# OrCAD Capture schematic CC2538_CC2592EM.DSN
size A3; title: CC2538-CC2592EM; rev: 2.0.1
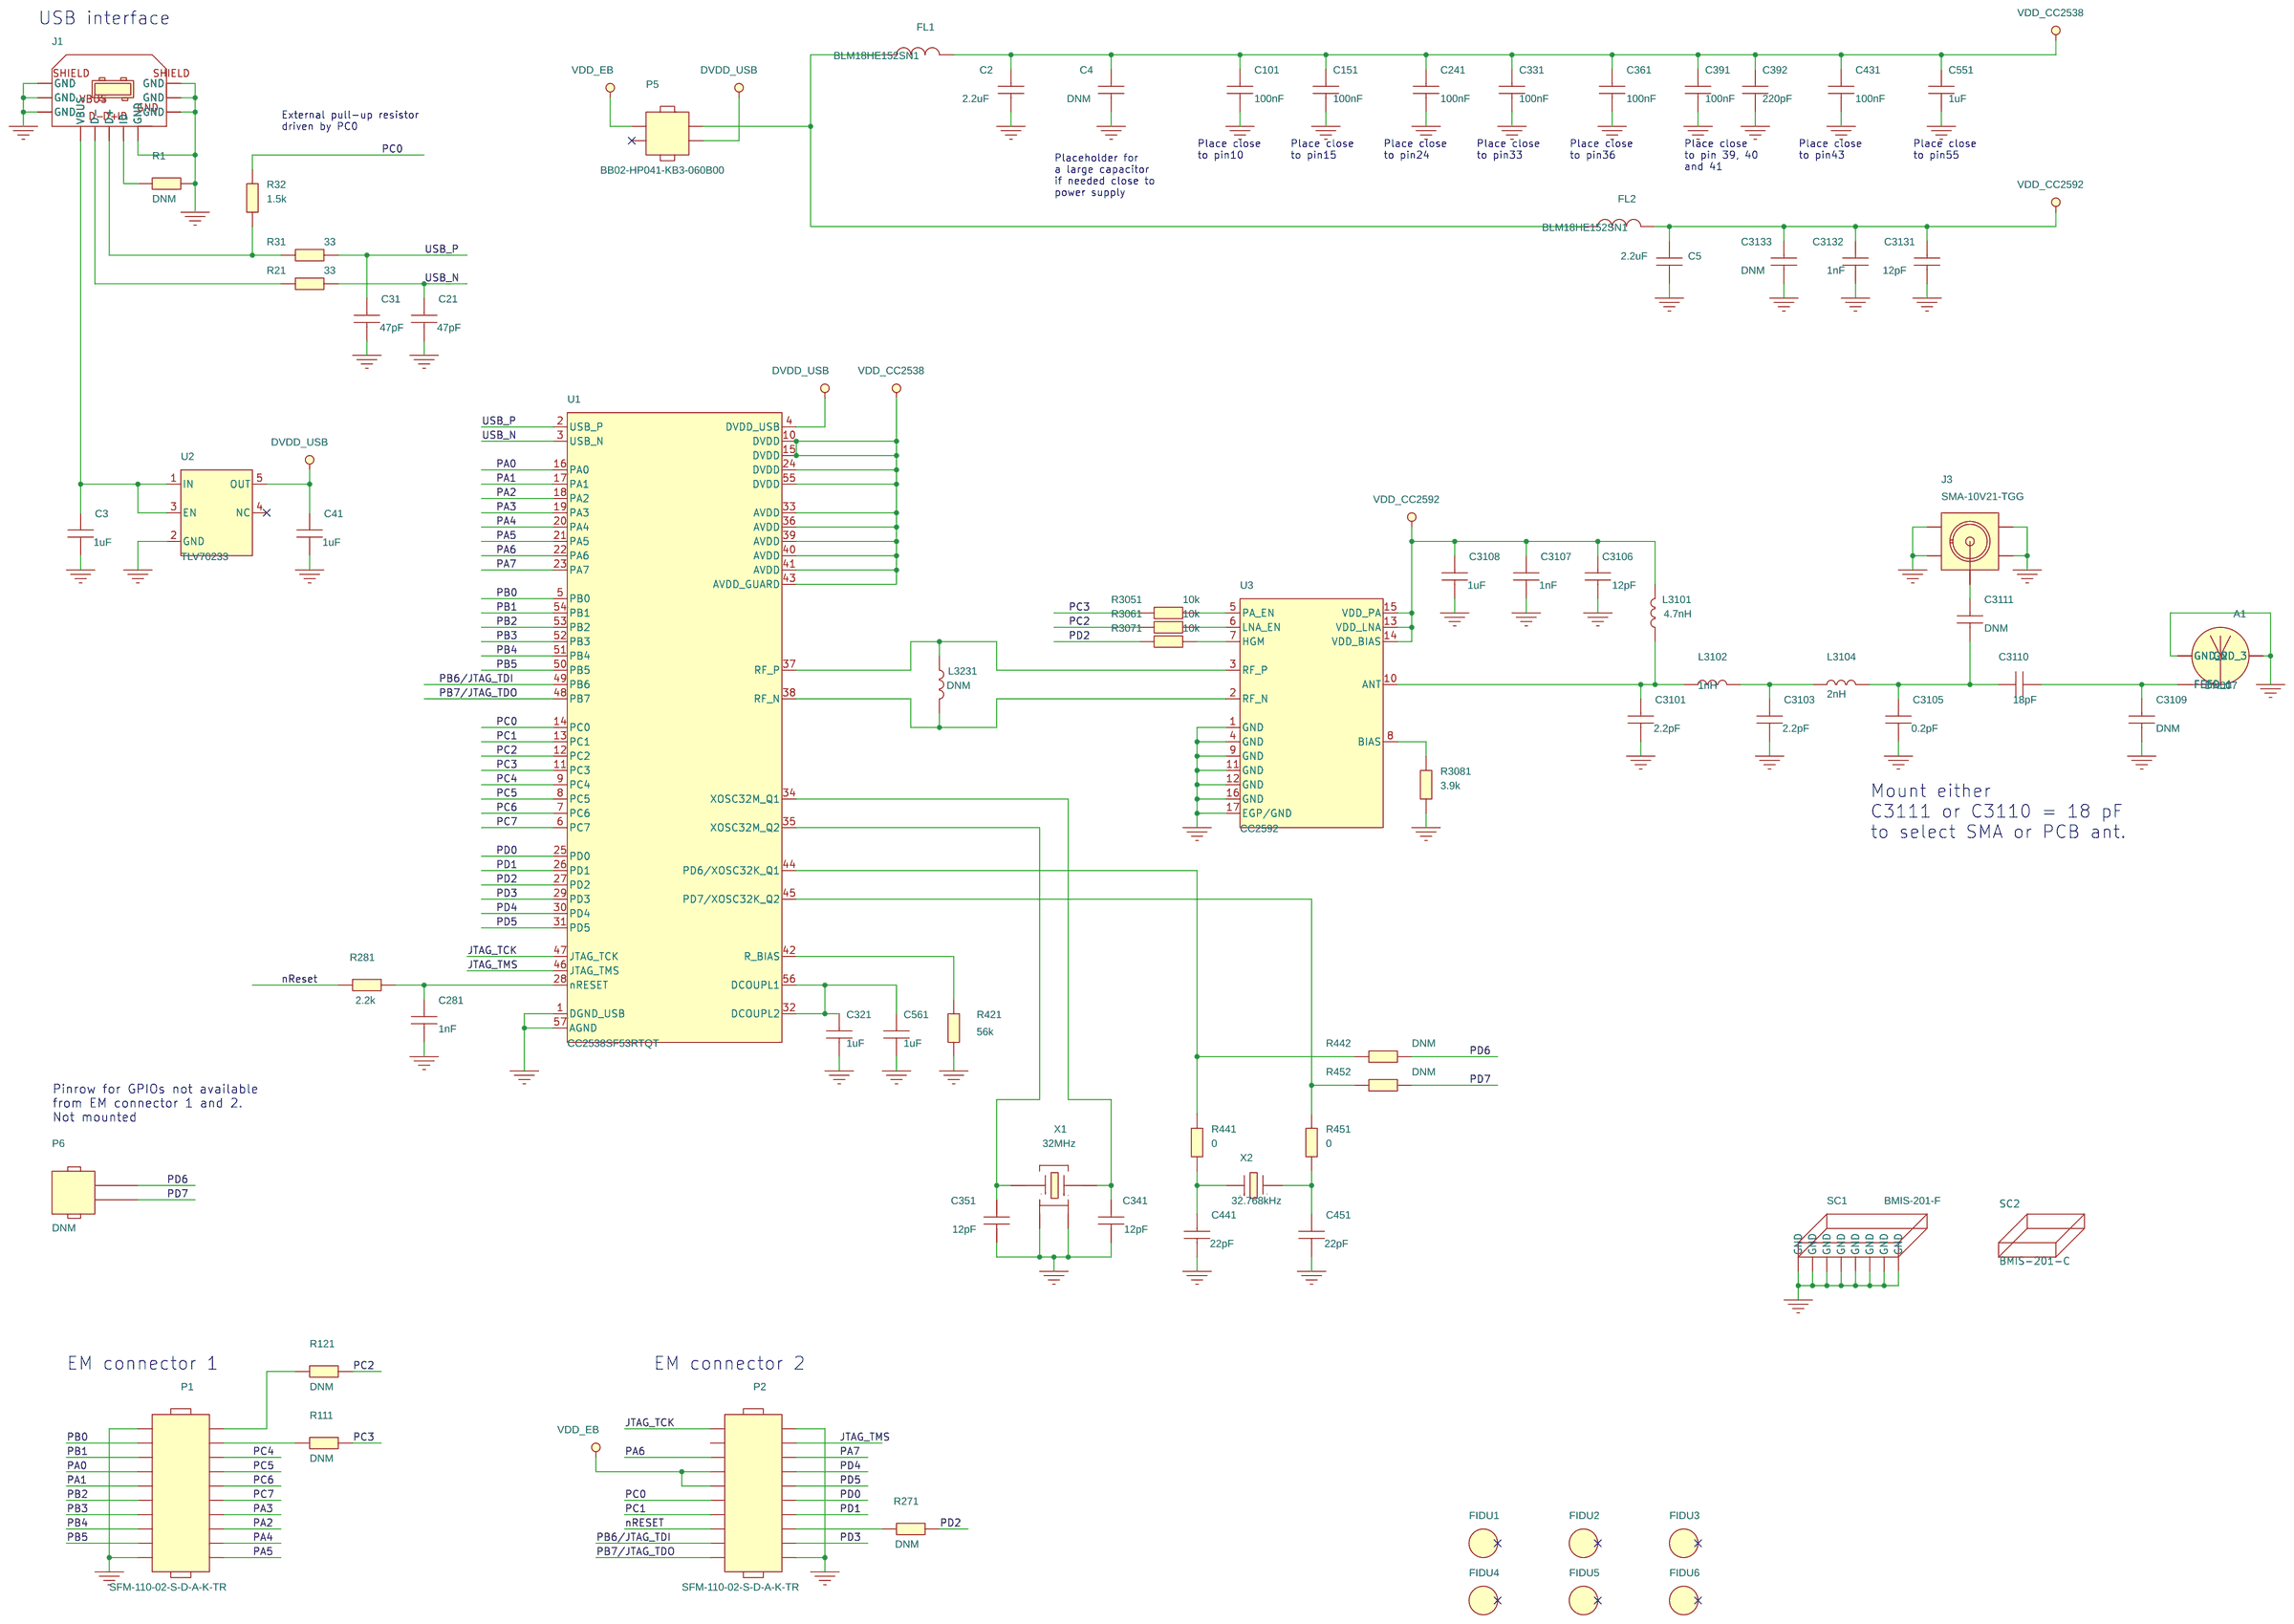
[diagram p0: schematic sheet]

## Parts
A1  DN007  [ANTENNA_DN007]
C2  2.2uF  [CAPC1608X90N]
C3  1uF  [CAPC1608X90N]
C4  DNM  [CAPC1608X90N]
C5  2.2uF  [CAPC1608X90N]
C21  47pF  [CAPC1005X60L]
C31  47pF  [CAPC1005X60L]
C41  1uF  [CAPC1608X90N]
C101  100nF  [CAPC1005X60L]
C151  100nF  [CAPC1005X60L]
C241  100nF  [CAPC1005X60L]
C281  1nF  [CAPC1005X60L]
C321  1uF  [CAPC1005X60L]
C331  100nF  [CAPC1005X60L]
C341  12pF  [CAPC1005X60L]
C351  12pF  [CAPC1005X60L]
C361  100nF  [CAPC1005X60L]
C391  100nF  [CAPC1005X60L]
C392  220pF  [CAPC1005X60L]
C431  100nF  [CAPC1005X60L]
C441  22pF  [CAPC1005X60L]
C451  22pF  [CAPC1005X60L]
C551  1uF  [CAPC1005X60L]
C561  1uF  [CAPC1005X60L]
C3101  2.2pF  [CAPC1005X60L]
C3103  2.2pF  [CAPC1005X60L]
C3105  0.2pF  [CAPC1005X60L]
C3106  12pF  [CAPC1005X60L]
C3107  1nF  [CAPC1005X60L]
C3108  1uF  [CAPC1005X60L]
C3109  DNM  [CAPC1005X60L]
C3110  18pF  [CAPC1005X60L]
C3111  DNM  [CAPC1005X60L]
C3131  12pF  [CAPC1005X60L]
C3132  1nF  [CAPC1005X60L]
C3133  DNM  [CAPC1005X60L]
FIDU1  FIDU_1MM  [FID100X115]
FIDU2  FIDU_1MM  [FID100X115]
FIDU3  FIDU_1MM  [FID100X115]
FIDU4  FIDU_1MM  [FID100X115]
FIDU5  FIDU_1MM  [FID100X115]
FIDU6  FIDU_1MM  [FID100X115]
FL1  BLM18HE152SN1  [FIL_BLM18HE152SN1DN]
FL2  BLM18HE152SN1  [FIL_BLM18HE152SN1DN]
J1  1981568-1  [TYCO_19815681N]
J3  SMA-10V21-TGG  [HUSTSAN_SMA10V21TGGAN]
L3101  4.7nH  [INDC1005X60L]
L3102  1nH  [INDC1005X60L]
L3104  2nH  [INDC1005X60L]
L3231  DNM  [INDC1005X60L]
P1  SFM-110-02-S-D-A-K-TR  [SAMTEC_SFM11002AN]
P2  SFM-110-02-S-D-A-K-TR  [SAMTEC_SFM11002AN]
P5  BB02-HP041-KB3-060B00  [GradConn_BB02HP041KB3060B00-4N]
P6  DNM  [TYCO_826629-2B]
R1  DNM  [RESC1005X40L]
R21  33  [RESC1005X40L]
R31  33  [RESC1005X40L]
R32  1.5k  [RESC1005X40L]
R111  DNM  [RESC1005X40L]
R121  DNM  [RESC1005X40L]
R271  DNM  [RESC1005X40L]
R281  2.2k  [RESC1005X40L]
R421  56k  [RESC1005X40L]
R441  0  [RESC1005X40L]
R442  DNM  [RESC1005X40L]
R451  0  [RESC1005X40L]
R452  DNM  [RESC1005X40L]
R3051  10k  [RESC1005X40L]
R3061  10k  [RESC1005X40L]
R3071  10k  [RESC1005X40L]
R3081  3.9k  [RESC1005X40L]
SC1  BMIS-201-F  [MECH_BMIS201F]
SC2  BMIS-201-C  [MECH_BMIS201C]
U1  CC2538SF53RTQT  [QFNFC50P800X800X100-57AN]
U2  TLV70233  [SOT95P280X145-5N]
U3  CC2592  [QFNFC65P400X400X100-17AN]
X1  32MHz  [XTAL_FA128N]
X2  32.768kHz  [XTAL_FC12MN]

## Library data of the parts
A1 = ANTENNA_DN007: MECHANIC, 2.4GHz INVERTED F ANTENNA, SMD; AutoDoc File: https://notefied-dynamic-precision.com/NotefiedWebServices/AutoDocs.aspx?itemid=85542; Datasheet URL 1: http://www.ti.com/lit/an/swru120b/swru120b.pdf; Datasheet URL 2: http://www.ti.com/lit/an/swru120b/swru120b.pdf; Frequency: 2.4GHz; MPN Status: ACTIVE; Manufacturer: TEXAS INSTRUMENTS; Mounting Type: SMD; NOTE Status: PREFERRED; Part Number: 13-00347; Part Type: MECHANIC\ANTENNA; Revision: R001; RoHS Status: PART NOT KNOWN
C2 C5 = CAPACITOR: CAPACITOR, CERAMIC X5R, 2.2uF, 10V, -20%/+20%, -55DEGC/+85DEGC, 0603, SMD; Alt IPC Footprints: CAPC1608X90L,CAPC1608X90M; AutoDoc File: https://notefied-dynamic-precision.com/NotefiedWebServices/AutoDocs.aspx?itemid=50283; Datasheet URL 1: http://www.murata.com/catalog/c02e13.pdf; Datasheet URL 2: http://www.murata.com/catalog/c02e13.pdf; Dielectric Type: X5R; Lead Time: 22; LifeCycle Status: GROWTH; MPN: GRM188R61A225ME34D; MPN Status: ACTIVE; Manufacturer: MURATA; Max Oper Temp: +85DEGC; Max Tol: +20%; Min Oper Temp: -55DEGC; Min Tol: -20%; Mounting Type: SMD; NOTE Status: PREFERRED; Old Footprint: CAPC1608X90N,0603; PCB Package: 0603; Part Number: 02-01132; Part Type: CAPACITOR\CERAMIC\0603; Revision: R001; RoHS Status: ROHS_COMPLIANT; Rtd Voltage: 10V
C3 C41 = CAPACITOR: CAPACITORS, CERAMIC, 1uF, 15%, X5R, 10V, 0603, SMD; Alt IPC Footprints: CAPC1608X90L,CAPC1608X90M; AutoDoc File: https://notefied-dynamic-precision.com/NotefiedWebServices/AutoDocs.aspx?itemid=50540; Budget Currency: EUR; Budget Price: 0.048; Datasheet URL 1: http://search.murata.co.jp/Ceramy/image/img/PDF/ENG/GRM188R61A105KA61.pdf; Datasheet URL 2: http://search.murata.co.jp/Ceramy/image/img/PDF/ENG/GRM188R61A105KA61.pdf; Dielectric Type: X5R; Lead Time: 26; LifeCycle Status: GROWTH; MPN: GRM188R61A105KA61D; MPN Status: ACTIVE; Manufacturer: MURATA; Max Oper Temp: +85DEGC; Max Tol: +10%; Min Oper Temp: -55DEGC; Min Tol: -10%; Mounting Type: SMD; NOTE Status: PREFERRED; Old Footprint: CAPC1608X90N,0603; PCB Package: 0603; Packing Size: 4000; Packing Type: TAPE_&_REEL; Part Number: 02-01389; Part Type: CAPACITOR\CERAMIC\0603; Revision: R002; RoHS Status: ROHS_COMPLIANT; Rtd Voltage: 10V
C4 = CAPACITOR: CAPACITOR, DO NOT MOUNT, 0603, SMD; ALT_SYMBOLS: CAPC1608X90L,CAPC1608X90M; AutoDoc File: https://notefied-dynamic-precision.com/NotefiedWebServices/AutoDocs.aspx?itemid=50475; Old Footprint: CAPC1608X90N,0603; Part Number: 02-01324; Part Type: CAPACITOR\CERAMIC\0603; Revision: R003
C21 C31 = CAPACITOR: CAPACITOR, CERAMIC C0G/NP0, 47pF, 50V, -5%/+5%, -55DEGC/+125DEGC, 0402, SMD; ALT_SYMBOLS: CAPC1005X60L,CAPC1005X60M; AutoDoc File: http://notefied-dynamic-precision.com/DB/Apps/Desktop/Item/Object.aspx?id=86073; Budget Currency: USD; Budget Price: 0.004; Datasheet URL 1: http://search.murata.co.jp/Ceramy/image/img/PDF/ENG/GRM1555C1H470JA01.pdf; Datasheet URL 2: http://search.murata.co.jp/Ceramy/image/img/PDF/ENG/GRM1555C1H470JA01.pdf; Dielectric Type: C0G/NP0; FPLIST: CAPC1005X60N,CAPC1005X60L,CAPC1005X60M; MPN: GRM1555C1H470JA01D; MPN Status: ACTIVE; Manufacturer: MURATA; Max Oper Temp: +125DEGC; Max TC: +30PPM/DEGC; Max Tol: +5%; Min Oper Temp: -55DEGC; Min TC: -30PPM/DEGC; Min Tol: -5%; Mounting Type: SMD; NOTE Status: PREFERRED; Old Footprint: CAPC1005X60N; PCB Package: 0402; Packing Size: 10000; Packing Type: TAPE_&_REEL; Part Number: 02-04366; Part Type: CAPACITOR\CERAMIC\0402; Revision: R001; RoHS Status: ROHS_COMPLIANT; Rtd Voltage: 50V
C101 C151 C241 C331 C361 C391 C431 = CAPACITOR: CAPACITOR, CERAMIC X7R, 100nF, 6.3V, -10%/+10%, -55DEGC/+125DEGC, 0402, SMD; ALT_SYMBOLS: CAPC1005X60L,CAPC1005X60M; AutoDoc File: http://notefied-dynamic-precision.com/DB/Apps/Desktop/Item/Object.aspx?id=73748; Budget Currency: USD; Budget Price: 0.0026; Datasheet URL 1: http://search.murata.co.jp/Ceramy/image/img/PDF/ENG/GRM155R70J104KA01.pdf; Datasheet URL 2: http://search.murata.co.jp/Ceramy/image/img/PDF/ENG/GRM155R70J104KA01.pdf; Dielectric Type: X7R; FPLIST: CAPC1005X60N,CAPC1005X60L,CAPC1005X60M; Lead Time: 12; LifeCycle Status: ACTIVE; MPN: GRM155R70J104KA01D; MPN Status: ACTIVE; Manufacturer: MURATA; Max Oper Temp: +125DEGC; Max Tol: +10%; Min Oper Temp: -55DEGC; Min Tol: -10%; Mounting Type: SMD; NOTE Status: PREFERRED; Old Footprint: CAPC1005X60N,0402; PCB Package: 0402; Packing Size: 10000; Packing Type: TAPE_&_REEL; Part Number: 02-02323; Part Type: CAPACITOR\CERAMIC\0402; Revision: R000; RoHS Status: ROHS_COMPLIANT; Rtd Voltage: 6.3V
C281 = CAPACITOR: CAPACITOR, CERAMIC X7R, 1nF, 50V, -10%/+10%, -55DEGC/+125DEGC, 0402, SMD; ALT_SYMBOLS: CAPC1005X60L,CAPC1005X60M; AutoDoc File: http://notefied-dynamic-precision.com/DB/Apps/Desktop/Item/Object.aspx?id=72148; Budget Currency: EUR; Budget Price: 0.016; Datasheet URL 1: http://www.murata.com/catalog/c02e13.pdf; Datasheet URL 2: http://search.murata.co.jp/Ceramy/image/img/PDF/ENG/GRM155R71H102KA01.pdf; Dielectric Type: X7R; FPLIST: CAPC1005X60N,CAPC1005X60L,CAPC1005X60M; Lead Time: 12; LifeCycle Status: GROWTH; MPN: GRM155R71H102KA01D; MPN Status: ACTIVE; Manufacturer: MURATA; Max Oper Temp: +125DEGC; Max Tol: +10%; Min Oper Temp: -55DEGC; Min Tol: -10%; Mounting Type: SMD; NOTE Status: PREFERRED; Old Footprint: CAPC1005X60N,0402; PCB Package: 0402; Packing Size: 10000; Packing Type: TAPE_&_REEL; Part Number: 02-02070; Part Type: CAPACITOR\CERAMIC\0402; Revision: R000; RoHS Status: ROHS_COMPLIANT; Rtd Voltage: 50V
C321 C551 C561 = CAPACITOR: CAPACITOR, CERAMIC X5R, 1uF, 10V, -10%/+10%, -55DEGC/+85DEGC, 0402, SMD; ALT_SYMBOLS: CAPC1005X60L,CAPC1005X60M; AutoDoc File: http://notefied-dynamic-precision.com/DB/Apps/Desktop/Item/Object.aspx?id=74236; Budget Currency: EUR; Budget Price: 0.066; Datasheet URL 1: http://search.murata.co.jp/Ceramy/image/img/PDF/ENG/GRM155R61A105KE15.pdf; Datasheet URL 2: http://search.murata.co.jp/Ceramy/image/img/PDF/ENG/GRM155R61A105KE15.pdf; Dielectric Type: X5R; FPLIST: CAPC1005X60N,CAPC1005X60L,CAPC1005X60M; MPN: GRM155R61A105KE15D; MPN Status: ACTIVE; Manufacturer: MURATA; Max Oper Temp: +85DEGC; Max Tol: +10%; Min Oper Temp: -55DEGC; Min Tol: -10%; Mounting Type: SMD; NOTE Status: PREFERRED; Old Footprint: CAPC1005X60N,0402; PCB Package: 0402; Packing Size: 10000; Packing Type: TAPE_&_REEL; Part Number: 02-02381; Part Type: CAPACITOR\CERAMIC\0402; Revision: R002; RoHS Status: ROHS_COMPLIANT; Rtd Voltage: 10V
C341 C351 = CAPACITOR: CAPACITOR, CERAMIC C0G/NP0, 12pF, 50V, -5%/+5%, -55DEGC/+125DEGC, 0402, SMD; ALT_SYMBOLS: CAPC1005X60L,CAPC1005X60M; AutoDoc File: http://notefied-dynamic-precision.com/DB/Apps/Desktop/Item/Object.aspx?id=84867; Datasheet URL 1: http://search.murata.co.jp/Ceramy/image/img/PDF/ENG/GRM1555C1H120JA01.pdf; Datasheet URL 2: http://search.murata.co.jp/Ceramy/image/img/PDF/ENG/GRM1555C1H120JA01.pdf; Dielectric Type: C0G/NP0; FPLIST: CAPC1005X60N,CAPC1005X60L,CAPC1005X60M; MPN: GRM1555C1H120JA01D; MPN Status: ACTIVE; Manufacturer: MURATA; Max Oper Temp: +125DEGC; Max TC: +30PPM/DEGC; Max Tol: +5%; Min Oper Temp: -55DEGC; Min TC: -30PPM/DEGC; Min Tol: -5%; Mounting Type: SMD; NOTE Status: PREFERRED; Old Footprint: CAPC1005X60N; PCB Package: 0402; Packing Size: 10000; Packing Type: TAPE_&_REEL; Part Number: 02-04168; Part Type: CAPACITOR\CERAMIC\0402; Revision: R000; RoHS Status: ROHS_COMPLIANT; Rtd Voltage: 50V
C392 = CAPACITOR: CAPACITOR, CERAMIC C0G/NP0, 220pF, 50V, -5%/+5%, -55DEGC/+125DEGC, 0402, SMD; ALT_SYMBOLS: CAPC1005X60L,CAPC1005X60M; AutoDoc File: http://notefied-dynamic-precision.com/DB/Apps/Desktop/Item/Object.aspx?id=50427; Budget Currency: EUR; Budget Price: 0.034; Datasheet URL 1: http://www.murata.com/catalog/c02e.pdf; Datasheet URL 2: http://www.murata.com/catalog/c02e.pdf; Dielectric Type: C0G/NP0; FPLIST: CAPC1005X60N,CAPC1005X60L,CAPC1005X60M; Lead Time: 12; LifeCycle Status: GROWTH; MPN: GRM1555C1H221JA01D; MPN Status: ACTIVE; Manufacturer: MURATA; Max Oper Temp: +125DEGC; Max Tol: +5%; Min Oper Temp: -55DEGC; Min Tol: -5%; Mounting Type: SMD; NOTE Status: PREFERRED; Old Footprint: CAPC1005X60N,0402; PCB Package: 0402; Packing Size: 10000; Packing Type: TAPE_&_REEL; Part Number: 02-01276; Part Type: CAPACITOR\CERAMIC\0402; Revision: R001; RoHS Status: ROHS_COMPLIANT; Rtd Voltage: 50V
C441 C451 = CAPACITOR: CAPACITOR, CERAMIC C0G/NP0, 22pF, 50V, -5%/+5%, -55DEGC/+125DEGC, 0402, SMD; ALT_SYMBOLS: CAPC1005X60L,CAPC1005X60M; AutoDoc File: http://notefied-dynamic-precision.com/DB/Apps/Desktop/Item/Object.aspx?id=86084; Budget Currency: EUR; Budget Price: 0.003; Datasheet URL 1: http://search.murata.co.jp/Ceramy/image/img/PDF/ENG/GRM1555C1H220JA01.pdf; Datasheet URL 2: http://search.murata.co.jp/Ceramy/image/img/PDF/ENG/GRM1555C1H220JA01.pdf; Dielectric Type: C0G/NP0; FPLIST: CAPC1005X60N,CAPC1005X60L,CAPC1005X60M; Lead Time: 10; MPN: GRM1555C1H220JA01D; MPN Status: ACTIVE; Manufacturer: MURATA; Max Oper Temp: +125DEGC; Max TC: +30PPM/DEGC; Max Tol: +5%; Min Oper Temp: -55DEGC; Min TC: -30PPM/DEGC; Min Tol: -5%; Mounting Type: SMD; NOTE Status: PREFERRED; Old Footprint: CAPC1005X60N; PCB Package: 0402; Packing Size: 10000; Packing Type: TAPE_&_REEL; Part Number: 02-04373; Part Type: CAPACITOR\CERAMIC\0402; Revision: R001; RoHS Status: ROHS_COMPLIANT; Rtd Voltage: 50V; WEIGHT: 0.0016g
C3101 C3103 = CAPACITOR: CAPACITOR, CERAMIC C0G/NP0, 2.2pF, 50V, -0.25pF/+0.25pF, -55DEGC/+125DEGC, 0402, SMD; ALT_SYMBOLS: CAPC1005X60L,CAPC1005X60M; AutoDoc File: http://notefied-dynamic-precision.com/DB/Apps/Desktop/Item/Object.aspx?id=87251; Budget Currency: EUR; Budget Price: 0.005; Datasheet URL 1: http://search.murata.co.jp/Ceramy/image/img/w_hinm/L0005E.pdf; Datasheet URL 2: http://psearch.murata.com/capacitor/product/GRM1555C1H2R2CA01%23.pdf; Definied Quality: INDUSTRIAL; Dielectric Type: C0G/NP0; Esd Level: N/A; FPLIST: CAPC1005X60N,CAPC1005X60L,CAPC1005X60M; Last Time Buy: N/A; Lead Time: 12; MPN: GRM1555C1H2R2CA01D; MPN Status: ACTIVE; MSL: 1; MTBF: N/A; MTBF Standard: N/A; Manufacturer: MURATA; Max Oper Temp: +125DEGC; Max Tol: +0.25pF; Min Oper Temp: -55DEGC; Min Tol: -0.25pF; Mounting Type: SMD; NOTE Status: PREFERRED; Old Footprint: CAPC1005X60N; PCB Package: 0402; Packing Size: 10000; Packing Type: TAPE_&_REEL; Part Number: 02-04605; Part Type: CAPACITOR\CERAMIC\0402; Revision: R001; RoHS Status: ROHS_COMPLIANT; Rtd Voltage: 50V; WEIGHT: 0.0016g
C3105 = CAPACITOR: CAPACITOR, CERAMIC C0G/NP0, 0.2pF, 50V, -5%/+5%, -55DEGC/+125DEGC, 0402, SMD; ALT_SYMBOLS: CAPC1005X60L,CAPC1005X60M; AutoDoc File: http://notefied-dynamic-precision.com/DB/Apps/Desktop/Item/Object.aspx?id=84863; Budget Currency: EUR; Budget Price: 0.005; Datasheet URL 1: http://search.murata.co.jp/Ceramy/image/img/w_hinm/L0005E.pdf; Datasheet URL 2: http://psearch.murata.com/capacitor/product/GRM1555C1HR20BA01%23.pdf; Definied Quality: INDUSTRIAL; Dielectric Type: C0G/NP0; Esd Level: N/A; FPLIST: CAPC1005X60N,CAPC1005X60L,CAPC1005X60M; Last Time Buy: N/A; Lead Time: 12; MPN: GRM1555C1HR20BA01D; MPN Status: ACTIVE; MSL: 1; MTBF: N/A; MTBF Standard: N/A; Manufacturer: MURATA; Max Oper Temp: +125DEGC; Max TC: +30PPM/DEGC; Max Tol: +5%; Min Oper Temp: -55DEGC; Min TC: -30PPM/DEGC; Min Tol: -5%; Mounting Type: SMD; NOTE Status: PREFERRED; Old Footprint: CAPC1005X60N; PCB Package: 0402; Packing Size: 10000; Packing Type: TAPE_&_REEL; Part Number: 02-04165; Part Type: CAPACITOR\CERAMIC\0402; Revision: R001; RoHS Status: ROHS_COMPLIANT; Rtd Voltage: 50V; WEIGHT: 0.0016g
C3106 C3131 = CAPACITOR: CAPACITOR, CERAMIC C0G/NP0, 12pF, 50V, -5%/+5%, -55DEGC/+125DEGC, 0402, SMD; ALT_SYMBOLS: CAPC1005X60L,CAPC1005X60M; AutoDoc File: http://notefied-dynamic-precision.com/DB/Apps/Desktop/Item/Object.aspx?id=84867; Budget Currency: EUR; Budget Price: 0.004; Datasheet URL 1: http://search.murata.co.jp/Ceramy/image/img/w_hinm/L0005E.pdf; Datasheet URL 2: http://psearch.murata.com/capacitor/product/GRM1555C1H120JA01%23.pdf; Definied Quality: INDUSTRIAL; Dielectric Type: C0G/NP0; Esd Level: N/A; FPLIST: CAPC1005X60N,CAPC1005X60L,CAPC1005X60M; Last Time Buy: N/A; Lead Time: 10; MPN: GRM1555C1H120JA01D; MPN Status: ACTIVE; MSL: 1; MTBF: N/A; MTBF Standard: N/A; Manufacturer: MURATA; Max Oper Temp: +125DEGC; Max TC: +30PPM/DEGC; Max Tol: +5%; Min Oper Temp: -55DEGC; Min TC: -30PPM/DEGC; Min Tol: -5%; Mounting Type: SMD; NOTE Status: PREFERRED; Old Footprint: CAPC1005X60N; PCB Package: 0402; Packing Size: 10000; Packing Type: TAPE_&_REEL; Part Number: 02-04168; Part Type: CAPACITOR\CERAMIC\0402; Revision: R000; RoHS Status: ROHS_COMPLIANT; Rtd Voltage: 50V; WEIGHT: 0.0016g
C3107 = CAPACITOR: CAPACITOR, CERAMIC C0G/NP0, 1nF, 50V, -5%/+5%, -55DEGC/+125DEGC, 0402, SMD; ALT_SYMBOLS: CAPC1005X60L,CAPC1005X60M; AutoDoc File: http://notefied-dynamic-precision.com/DB/Apps/Desktop/Item/Object.aspx?id=88013; Budget Currency: USD; Budget Price: 0.00589; Datasheet URL 1: N/A; Datasheet URL 2: N/A; Definied Quality: INDUSTRIAL; Dielectric Type: C0G/NP0; Esd Level: N/A; FPLIST: CAPC1005X60N,CAPC1005X60L,CAPC1005X60M; Last Time Buy: N/A; Lead Time: N/A; MPN: CAPACITOR_0402_1nF_C0G/NP0_M_+/-5%_50V; MPN Status: ACTIVE; MSL: N/A; MTBF: N/A; MTBF Standard: N/A; Manufacturer: MANUFACTURER SELECTION; Max Oper Temp: +125DEGC; Max Tol: +5%; Min Oper Temp: -55DEGC; Min Tol: -5%; Mounting Type: SMD; NOTE Status: PREFERRED; Old Footprint: CAPC1005X60N; PCB Package: 0402; Packing Size: 10000; Packing Type: TAPE_&_REEL; Part Number: 02-04728; Part Type: CAPACITOR\CERAMIC\0402; Revision: R001; RoHS Status: ROHS_COMPLIANT; Rtd Voltage: 50V; WEIGHT: N/A
C3108 = CAPACITOR: CAPACITOR, CERAMIC X5R, 1uF, 10V, -10%/+10%, -55DEGC/+85DEGC, 0402, SMD; ALT_SYMBOLS: CAPC1005X60L,CAPC1005X60M; AutoDoc File: http://notefied-dynamic-precision.com/DB/Apps/Desktop/Item/Object.aspx?id=74236; Budget Currency: EUR; Budget Price: 0.016; Datasheet URL 1: http://search.murata.co.jp/Ceramy/image/img/w_hinm/L0005E.pdf; Datasheet URL 2: http://psearch.murata.com/capacitor/product/GRM155R61A105KE15%23.pdf; Definied Quality: INDUSTRIAL; Dielectric Type: X5R; Esd Level: N/A; FPLIST: CAPC1005X60N,CAPC1005X60L,CAPC1005X60M; Last Time Buy: N/A; Lead Time: 14; MPN: GRM155R61A105KE15D; MPN Status: ACTIVE; MSL: 1; MTBF: N/A; MTBF Standard: N/A; Manufacturer: MURATA; Max Oper Temp: +85DEGC; Max Tol: +10%; Min Oper Temp: -55DEGC; Min Tol: -10%; Mounting Type: SMD; NOTE Status: PREFERRED; Old Footprint: CAPC1005X60N,0402; PCB Package: 0402; Packing Size: 10000; Packing Type: TAPE_&_REEL; Part Number: 02-02381; Part Type: CAPACITOR\CERAMIC\0402; Revision: R002; RoHS Status: ROHS_COMPLIANT; Rtd Voltage: 10V; WEIGHT: 0.0016g
C3109 C3111 C3133 = CAPACITOR: CAPACITOR, DO NOT MOUNT, 0402, SMD; ALT_SYMBOLS: CAPC1005X60L,CAPC1005X60M; AutoDoc File: https://notefied-dynamic-precision.com/NotefiedWebServices/AutoDocs.aspx?itemid=50472; FPLIST: CAPC1005X60N,CAPC1005X60L,CAPC1005X60M; Old Footprint: CAPC1005X60N,0402; Part Number: 02-01321; Part Type: CAPACITOR\CERAMIC\0402; Revision: R003
C3110 = CAPACITOR: CAPACITOR, CERAMIC C0G/NPO, 18pF, 50V, -55DEGC/+125DEGC, 0402, SMD; ALT_SYMBOLS: CAPC1005X60L,CAPC1005X60M; AutoDoc File: http://notefied-dynamic-precision.com/DB/Apps/Desktop/Item/Object.aspx?id=74533; Budget Currency: USD; Budget Price: 0.0051; Datasheet URL 1: http://search.murata.co.jp/Ceramy/image/img/w_hinm/L0005E.pdf; Datasheet URL 2: http://psearch.murata.com/capacitor/product/GRM1555C1H180JA01%23.pdf; Definied Quality: INDUSTRIAL; Dielectric Type: C0G/NP0; Esd Level: N/A; FPLIST: CAPC1005X60N,CAPC1005X60L,CAPC1005X60M; Last Time Buy: N/A; Lead Time: 10; MPN: GRM1555C1H180JA01D; MPN Status: ACTIVE; MSL: 1; MTBF: N/A; MTBF Standard: N/A; Manufacturer: MURATA; Max Oper Temp: +125DEGC; Max Tol: +5%; Min Oper Temp: -55DEGC; Min Tol: -5%; Mounting Type: SMD; NOTE Status: PREFERRED; Old Footprint: CAPC1005X60N; PCB Package: 0402; Packing Size: 10000; Packing Type: TAPE_&_REEL; Part Number: 02-02407; Part Type: CAPACITOR\CERAMIC\0402; Revision: R002; RoHS Status: ROHS_COMPLIANT; Rtd Voltage: 50V; WEIGHT: 0.0016g
C3132 = CAPACITOR: CAPACITOR, CERAMIC X7R, 1nF, 50V, -5%/+5%, -55DEGC/+125DEGC, 0402, SMD; ALT_SYMBOLS: CAPC1005X60L,CAPC1005X60M; AutoDoc File: http://notefied-dynamic-precision.com/DB/Apps/Desktop/Item/Object.aspx?id=80112; Budget Currency: USD; Budget Price: 0.00589; Dielectric Type: X7R; FPLIST: CAPC1005X60N,CAPC1005X60L,CAPC1005X60M; LifeCycle Status: ACTIVE; MPN: CAPACITOR_0402_1nF_X7R_M_+/-5%_50V; MPN Status: ACTIVE; Manufacturer: Manufacturer selection; Max Oper Temp: +125DEGC; Max Tol: +5%; Min Oper Temp: -55DEGC; Min Tol: -5%; Mounting Type: SMD; NOTE Status: PREFERRED; Old Footprint: CAPC1005X60N; PCB Package: 0402; Packing Size: 10000; Packing Type: TAPE_&_REEL; Part Number: 02-03019; Part Type: CAPACITOR\CERAMIC\0402; Revision: R000; RoHS Status: ROHS_COMPLIANT; Rtd Voltage: 50V
FIDU1-FIDU6 = FIDMARK: FIDUCIAL MARK, ROUND 1MM; AutoDoc File: https://notefied-dynamic-precision.com/NotefiedWebServices/AutoDocs.aspx?itemid=74548; Part Number: 19-00111; Part Type: NON_COMPONENT\FIDUCIAL; Revision: R001
FL1 = FILTER_2PIN: FILTER, EMI, 1500@100MHz, -55DEGC/+125DEGC, 0603, SMD; Alt IPC Footprints: FIL_BLM18HE152SN1DL,FIL_BLM18HE152SN1DM; AutoDoc File: https://notefied-dynamic-precision.com/NotefiedWebServices/AutoDocs.aspx?itemid=85575; Datasheet URL 1: http://www.murata.com/products/catalog/pdf/c31e.pdf#BLM18H; Datasheet URL 2: http://www.murata.com/products/catalog/pdf/c31e.pdf#BLM18H; Impedance: 1500@100MHz; MPN: BLM18HE152SN1D; MPN Status: ACTIVE; Manufacturer: MURATA; Max Oper Temp: +125DEGC; Max Tol: +25%; Min Oper Temp: -55DEGC; Min Tol: -25%; Mounting Type: SMD; NOTE Status: PREFERRED; PCB Package: 0603; Packing Size: 4000; Packing Type: TAPE_&_REEL; Part Number: 04-00470; Part Type: FILTER\EMI\0603; Revision: R001; RoHS Status: ROHS_COMPLIANT; Rtd Current: 0.5A
FL2 = FILTER_2PIN: FILTER, EMI, 1500@100MHz, -55DEGC/+125DEGC, 0603, SMD; ALT_SYMBOLS: FIL_BLM18HE152SN1DL,FIL_BLM18HE152SN1DM; AutoDoc File: http://notefied-dynamic-precision.com/DB/Apps/Desktop/Item/Object.aspx?id=85575; Datasheet URL 1: http://notefied-dynamic-precision.com/DB/Apps/Desktop/Item/Object.aspx?id=85575; Datasheet URL 2: http://notefied-dynamic-precision.com/DB/Apps/Desktop/Item/Object.aspx?id=85575; Impedance: 1500@100MHz; MPN: BLM18HE152SN1D; MPN Status: ACTIVE; Manufacturer: MURATA; Max Oper Temp: +125DEGC; Max Tol: +25%; Min Oper Temp: -55DEGC; Min Tol: -25%; Mounting Type: SMD; NOTE Status: PREFERRED; PCB Package: 0603; Packing Size: 4000; Packing Type: TAPE_&_REEL; Part Number: 04-00470; Part Type: FILTER\EMI\0603; Revision: R001; RoHS Status: ROHS_COMPLIANT; Rtd Current: 0.5A
J1 = CONN_USB_MICRO_5+6_S: CONNECTOR, USB-B, 5 PINS, PITCH 0.65mm, SMD; Alt IPC Footprints: TYCO_19815681L,TYCO_19815681M; AutoDoc File: https://notefied-dynamic-precision.com/NotefiedWebServices/AutoDocs.aspx?itemid=85543; Datasheet URL 1: http://www.te.com/catalog/pn/en/1981568-1; Datasheet URL 2: http://www.te.com/catalog/pn/en/1981568-1; MPN Status: ACTIVE; Manufacturer: Tyco; Max Oper Temp: N/A; Min Oper Temp: N/A; Mounting Type: SMD; NOTE Status: PREFERRED; No Of Pos: 5; No Of Rows: 1; Packing Size: 1000; Packing Type: TAPE_&_REEL; Part Number: 06-02244; Part Type: CONNECTOR\USB; Pitch: 0.65mm; Revision: R001; RoHS Status: ROHS_COMPLIANT
J3 = CONN_COAX_1+4: CONNECTOR, COAX RF, STRAIGHT, FEMALE, 1 PIN, SMD; ALT_SYMBOLS: HUSTSAN_SMA10V21TGGL,HUSTSAN_SMA10V21TGGM; AutoDoc File: https://notefied-dynamic-precision.com/NotefiedWebServices/AutoDocs.aspx?itemid=84956; Datasheet URL 1: http://www.hustsan.com.tw/uploaddir/product/SMA-10V21.pdf; Datasheet URL 2: http://www.hustsan.com.tw/uploaddir/product/SMA-10V21.pdf; FPLIST: HUSTSAN_SMA10V21TGGAN,HUSTSAN_SMA10V21TGGN; MPN Status: ACTIVE; Manufacturer: HUS-TSAN; Mounting Type: SMD; NOTE Status: PREFERRED; No Of Pos: 1; Old Footprint: HUSTSAN_SMA10V21TGGAN,HUSTSAN_SMA10V21TGGN; Part Number: 06-02188; Part Type: CONNECTOR\COAX; Revision: R003
L3101 = INDUCTOR: INDUCTOR, CHIP, 4.7nH, -0.3nH/+0.3nH, 0.3A, -55DEGC/+125DEGC, 0402, SMD; ALT_SYMBOLS: INDC1005X60L,INDC1005X60M; AutoDoc File: http://notefied-dynamic-precision.com/DB/Apps/Desktop/Item/Object.aspx?id=87735; Budget Currency: EUR; Budget Price: 0.021; Datasheet URL 1: N/A; Datasheet URL 2: http://psearch.murata.com/inductor/product/LQG15HS4N7S02%23.pdf; Definied Quality: INDUSTRIAL; Esd Level: N/A; FPLIST: INDC1005X60N,INDC1005X60L,INDC1005X60M; Frequency: 6GHz; Last Time Buy: N/A; Lead Time: 7; MPN: LQG15HS4N7S02D; MPN Status: ACTIVE; MSL: N/A; MTBF: N/A; MTBF Standard: N/A; Manufacturer: MURATA; Max Oper Temp: +125DEGC; Max Tol: +0.3nH; Min Oper Temp: -55DEGC; Min Tol: -0.3nH; Mounting Type: SMD; NOTE Status: PREFERRED; Old Footprint: INDC1005X60N; PCB Package: 0402; Packing Size: 10000; Packing Type: TAPE_&_REEL; Part Number: 03-06631; Part Type: INDUCTOR\CHIP\0402; Resistance: 0.18; Revision: R001; RoHS Status: ROHS_COMPLIANT; Rtd Current: 0.3A; WEIGHT: 0.001g
L3102 = INDUCTOR_HOR: INDUCTOR, CHIP, 1nH, -0.3nH/+0.3nH, 0.3A, -55DEGC/+125DEGC, 0402, SMD; ALT_SYMBOLS: INDC1005X60L,INDC1005X60M; AutoDoc File: http://notefied-dynamic-precision.com/DB/Apps/Desktop/Item/Object.aspx?id=87398; Budget Currency: EUR; Budget Price: 0.017; Datasheet URL 1: N/A; Datasheet URL 2: http://psearch.murata.com/inductor/product/LQG15HS1N0S02%23.pdf; Definied Quality: INDUSTRIAL; Esd Level: N/A; FPLIST: INDC1005X60N,INDC1005X60L,INDC1005X60M; Frequency: 10GHz; Last Time Buy: N/A; Lead Time: 9; MPN: LQG15HS1N0S02D; MPN Status: ACTIVE; MSL: N/A; MTBF: N/A; MTBF Standard: N/A; Manufacturer: MURATA; Max Oper Temp: +125DEGC; Max Tol: +0.3nH; Min Oper Temp: -55DEGC; Min Tol: -0.3nH; Mounting Type: SMD; NOTE Status: PREFERRED; Old Footprint: INDC1005X60N; PCB Package: 0402; Packing Size: 10000; Packing Type: TAPE_&_REEL; Part Number: 03-06607; Part Type: INDUCTOR\CHIP\0402; Resistance: 0.07; Revision: R001; RoHS Status: ROHS_COMPLIANT; Rtd Current: 0.3A; WEIGHT: 0.001g
L3104 = INDUCTOR: INDUCTOR, CHIP, 2nH, -0.3nH/ +0.3nH, 0.3A, -55DEGC/+125DEGC, 0402, SMD; ALT_SYMBOLS: INDC1005X60L,INDC1005X60M; AutoDoc File: http://notefied-dynamic-precision.com/DB/Apps/Desktop/Item/Object.aspx?id=85431; Budget Currency: EUR; Budget Price: 0.025; Datasheet URL 1: N/A; Datasheet URL 2: http://psearch.murata.com/inductor/product/LQG15HS2N0S02%23.pdf; Definied Quality: INDUSTRIAL; Esd Level: N/A; FPLIST: INDC1005X60N,INDC1005X60L,INDC1005X60M; Frequency: 6GHz; Last Time Buy: N/A; Lead Time: 9; MPN: LQG15HS2N0S02D; MPN Status: ACTIVE; MSL: N/A; MTBF: N/A; MTBF Standard: N/A; Manufacturer: MURATA; Max Oper Temp: +125DEGC; Max Tol: +0.3nH; Min Oper Temp: -55DEGC; Min Tol: -0.3nH; Mounting Type: SMD; NOTE Status: PREFERRED; Old Footprint: INDC1005X60N; PCB Package: 0402; Packing Size: 10000; Packing Type: TAPE_&_REEL; Part Number: 03-06525; Part Type: INDUCTOR\CHIP\0402; Revision: R001; RoHS Status: ROHS_COMPLIANT; Rtd Current: 0.3A; WEIGHT: 0.001g
L3231 = INDUCTOR: INDUCTOR, TO BE DECIDED, 0402, SMD; ALT_SYMBOLS: INDC1005X60M,INDC1005X60L; AutoDoc File: https://notefied-dynamic-precision.com/NotefiedWebServices/AutoDocs.aspx?itemid=45714; FPLIST: INDC1005X60N,INDC1005X60M,INDC1005X60L; Old Footprint: 0402; Part Number: 03-01022; Part Type: INDUCTOR\CHIP\0402; Revision: R002
P1 P2 = CONN_HEADER_2X10_P_S: CONNECTOR, HEADER, FEMALE, STRAIGHT, 2 ROWS, 20 PINS, PITCH 1.27mm, SMD; Alt IPC Footprints: SAMTEC_SFM11002AL,SAMTEC_SFM11002AM; AutoDoc File: https://notefied-dynamic-precision.com/NotefiedWebServices/AutoDocs.aspx?itemid=85603; Datasheet URL 1: http://www.samtec.com/ProductInformation/TechnicalSpecifications/CatalogPages.aspx?series=SFM; Datasheet URL 2: http://www.samtec.com/documents/webfiles/cpdf/SFM-1XX-XX-XX-S-XX-MKT1.pdf; MPN: SFM-110-02-SM-D-A-K-TR; MPN Status: ACTIVE; Manufacturer: SAMTEC; Max Oper Temp: +125DEGC; Min Oper Temp: -55DEGC; Mounting Type: SMD; NOTE Status: PREFERRED; No Of Pos: 20; No Of Rows: 2; Packing Size: 125; Packing Type: TAPE_&_REEL; Part Number: 06-02251; Part Type: CONNECTOR\HEADER; Pitch: 1.27mm; Revision: R001; RoHS Status: ROHS_COMPLIANT
P5 = CONN_HEADER_2X2_P_S: CONNECTOR, HEADER, STRAIGHT, MALE, 4 PINS, 2 ROWS, 2.54mm PITCH, SMD; Alt IPC Footprints: GradConn_BB02HP041KB3060B00-4L,GradConn_BB02HP041KB3060B00-4M; AutoDoc File: https://notefied-dynamic-precision.com/NotefiedWebServices/AutoDocs.aspx?itemid=84962; Datasheet URL 1: http://www.gradconn.com/2-54mm/pdf/BB02-HP.pdf; Datasheet URL 2: http://www.gradconn.com/2-54mm/pdf/BB02-HP.pdf; MPN Status: ACTIVE; Manufacturer: GradConn Cable; Max Oper Temp: +105DEGC; Min Oper Temp: -40DEGC; Mounting Type: SMD; NOTE Status: PREFERRED; No Of Pos: 4; No Of Rows: 2; Packing Type: TUBE; Part Number: 06-02190; Part Type: CONNECTOR\HEADER; Pitch: 2.54mm; Revision: R001; RoHS Status: ROHS_COMPLIANT; Rtd Current: 3A
P6 = CONN_HEADER_2: CONNECTOR, HEADER, MALE, STRAIGHT, 1 ROW, 2 PINS, PITCH 2.54mm, PTH; ALT_SYMBOLS: TYCO_826629-2C,TYCO_826629-2A; AutoDoc File: https://notefied-dynamic-precision.com/NotefiedWebServices/AutoDocs.aspx?itemid=50729; Budget Currency: EUR; Budget Price: 0.1607; Datasheet URL 1: http://www.tycoelectronics.com/catalog/bin/TE.Connect?C=1&M=BYPN&TCPN=826629-2&RQPN=826629-2; Datasheet URL 2: http://www.tycoelectronics.com/catalog/bin/TE.Connect?C=1&M=BYPN&TCPN=826629-2&RQPN=826629-2; Lead Time: 7; LifeCycle Status: ACTIVE; MPN: 826629-2; MPN Status: ACTIVE; Manufacturer: AMP TYCO ELECTRONICS CORPORATION; Max Oper Temp: +105DEGC; Min Oper Temp: -65DEGC; Mounting Type: PTH; NOTE Status: PREFERRED; No Of Pos: 2; No Of Rows: 1; Part Number: 06-00059; Part Type: CONNECTOR\HEADER; Pitch: 2.54mm; Revision: R001; RoHS Status: ROHS_COMPLIANT; Rtd Current: 3A; Rtd Voltage: 750V
R1 R111 R121 R271 R442 R452 = RESISTOR: RESISTOR, DO NOT MOUNT, 0402, SMD; ALT_SYMBOLS: RESC1005X40L,RESC1005X40M; AutoDoc File: https://notefied-dynamic-precision.com/NotefiedWebServices/AutoDocs.aspx?itemid=48359; FPLIST: RESC1005X40N,RESC1005X40L,RESC1005X40M; Old Footprint: RESC1005X40N,0402; Part Number: 01-02475; Part Type: RESISTOR\0402; Revision: R002
R21 R31 = RESISTOR: RESISTOR, THICK FILM, 33, -1%/+1%, 0.063W, 50V, -55DEGC/+155DEGC, 0402, SMD; ALT_SYMBOLS: RESC1005X40L,RESC1005X40M; AutoDoc File: http://notefied-dynamic-precision.com/DB/Apps/Desktop/Item/Object.aspx?id=85520; Datasheet URL 1: http://de.mouser.com/search/ProductDetail.aspx?qs=pim%252bJ6MgNfTiDS8xgyPANA%3D%3D; Datasheet URL 2: http://www.koaspeer.com/pdfs/res5.pdf; FPLIST: RESC1005X40N,RESC1005X40L,RESC1005X40M; MPN: RK73H1ETTP33R0F; MPN Status: ACTIVE; Manufacturer: KOA SPEER; Max Oper Temp: +155DEGC; Max TC: +100PPM/DEGC; Max Tol: +1%; Min Oper Temp: -55DEGC; Min TC: -100PPM/DEGC; Min Tol: -1%; Mounting Type: SMD; NOTE Status: PREFERRED; Old Footprint: RESC1005X40N; PCB Package: 0402; Packing Type: TAPE_&_REEL; Part Number: 01-16853; Part Type: RESISTOR\0402\PRECISION; Resistor Type: THICK FILM; Revision: R001; RoHS Status: ROHS_COMPLIANT; Rtd Power: 0.063W; Rtd Voltage: 50V
R32 = RESISTOR: RESISTOR, THICK FILM, 1.5k, -1%/+1%, 0.063W, 50V, -55DEGC/+155DEGC, 0402, SMD; ALT_SYMBOLS: RESC1005X40L,RESC1005X40M; AutoDoc File: http://notefied-dynamic-precision.com/DB/Apps/Desktop/Item/Object.aspx?id=85521; Datasheet URL 1: http://de.mouser.com/ProductDetail/KOA-Speer/RK73H1ETTP1501F/?qs=sGAEpiMZZMu61qfTUdNhGxThjrFPLFHZuHTM8MUapcA%3d; Datasheet URL 2: http://www.koaspeer.com/pdfs/res5.pdf; FPLIST: RESC1005X40N,RESC1005X40L,RESC1005X40M; MPN: RK73H1ETTP1501F; MPN Status: ACTIVE; Manufacturer: KOA SPEER; Max Oper Temp: +155DEGC; Max TC: +100PPM/DEGC; Max Tol: +1%; Min Oper Temp: -55DEGC; Min TC: -100PPM/DEGC; Min Tol: -1%; Mounting Type: SMD; NOTE Status: PREFERRED; Old Footprint: RESC1005X40N; PCB Package: 0402; Packing Type: TAPE_&_REEL; Part Number: 01-16854; Part Type: RESISTOR\0402\PRECISION; Resistor Type: THICK FILM; Revision: R002; RoHS Status: ROHS_COMPLIANT; Rtd Power: 0.063W; Rtd Voltage: 50V
R281 = RESISTOR: RESISTOR, THICK FILM, 2.2k, -1%/+1%, 0.063W, 50V, -55DEGC/+155DEGC, 0402, SMD; ALT_SYMBOLS: RESC1005X40L,RESC1005X40M; AutoDoc File: http://notefied-dynamic-precision.com/DB/Apps/Desktop/Item/Object.aspx?id=74771; Budget Currency: EUR; Budget Price: 0.094; Datasheet URL 2: http://www.koaspeer.com/pdfs/res5.pdf; FPLIST: RESC1005X40N,RESC1005X40L,RESC1005X40M; Lead Time: 11; LifeCycle Status: ACTIVE; MPN: RK73H1ETTP2201F; MPN Status: ACTIVE; Manufacturer: KOA SPEER; Max Oper Temp: +155DEGC; Max TC: +100PPM/DEGC; Max Tol: +1%; Min Oper Temp: -55DEGC; Min TC: -100PPM/DEGC; Min Tol: -1%; Mounting Type: SMD; NOTE Status: PREFERRED; Old Footprint: RESC1005X40N; PCB Package: 0402; Packing Size: 10000; Packing Type: TAPE_&_REEL; Part Number: 01-11503; Part Type: RESISTOR\0402\PRECISION; Resistor Type: THICK FILM; Revision: R000; RoHS Status: ROHS_COMPLIANT; Rtd Power: 0.063W; Rtd Voltage: 50V
R421 = RESISTOR: RESISTOR, THICK FILM, 56k, -5%/+5%, 0.063W, 50V, -55DEGC/+155DEGC, 0402, SMD; ALT_SYMBOLS: RESC1005X40L,RESC1005X40M; AutoDoc File: http://notefied-dynamic-precision.com/DB/Apps/Desktop/Item/Object.aspx?id=47146; Budget Currency: USD; Budget Price: 0.001; Datasheet URL 1: http://www.vishay.com/docs/20035/dcrcwE3.pdf; Datasheet URL 2: http://www.vishay.com/docs/20035/dcrcwE3.pdf; FPLIST: RESC1005X40N,RESC1005X40L,RESC1005X40M; Lead Time: 10; LifeCycle Status: ACTIVE; MPN: CRCW040256K0JNED; MPN Status: ACTIVE; Manufacturer: VISHAY; Max Oper Temp: +155DEGC; Max TC: +200PPM; Max Tol: +5%; Min Oper Temp: -55DEGC; Min TC: -200PPM; Min Tol: -5%; Mounting Type: SMD; NOTE Status: PREFERRED; Old Footprint: RESC1005X40N,0402; PCB Package: 0402; Part Number: 01-01262; Part Type: RESISTOR\0402; Resistor Type: THICK FILM; Revision: R001; RoHS Status: ROHS_COMPLIANT; Rtd Power: 0.063W; Rtd Voltage: 50V
R441 R451 = RESISTOR: RESISTOR, JUMPER, -55DEGC/+155DEGC, 0402, SMD; ALT_SYMBOLS: RESC1005X40L,RESC1005X40M; AutoDoc File: http://notefied-dynamic-precision.com/DB/Apps/Desktop/Item/Object.aspx?id=47668; Datasheet URL 1: http://www.koaspeer.com/catimages/Products/RK73Z/RK73Z.pdf; Datasheet URL 2: http://www.koaspeer.com/catimages/Products/RK73Z/RK73Z.pdf; FPLIST: RESC1005X40N,RESC1005X40L,RESC1005X40M; Lead Time: 14; LifeCycle Status: ACTIVE; MPN: RK73Z1ETTP; MPN Status: ACTIVE; Manufacturer: KOA SPEER; Max Oper Temp: +155DEGC; Min Oper Temp: -55DEGC; Mounting Type: SMD; NOTE Status: PREFERRED; Old Footprint: RESC1005X40N,0402; PCB Package: 0402; Part Number: 01-01784; Part Type: RESISTOR\JUMPER\0402; Revision: R002; RoHS Status: ROHS_COMPLIANT; Rtd Current: 1A
R3051 R3061 R3071 = RESISTOR: RESISTOR, THICK FILM, 10k, -5%/+5%, 0.063W, 50V, -55DEGC/+155DEGC, 0402, SMD; ALT_SYMBOLS: RESC1005X40L,RESC1005X40M; AutoDoc File: http://notefied-dynamic-precision.com/DB/Apps/Desktop/Item/Object.aspx?id=47128; Budget Currency: EUR; Budget Price: 0.012; Datasheet URL 1: http://www.vishay.com/docs/20035/dcrcwE3.pdf; Datasheet URL 2: http://www.vishay.com/docs/20035/dcrcwe3.pdf; Definied Quality: INDUSTRIAL; FPLIST: RESC1005X40N,RESC1005X40L,RESC1005X40M; Lead Time: 12; LifeCycle Status: ACTIVE; MPN: CRCW040210K0JNED; MPN Status: ACTIVE; MSL: 1; MTBF: 1.00*10^10; MTBF Standard: CL=90%; Manufacturer: VISHAY; Max Oper Temp: +155DEGC; Max TC: +200PPM; Max Tol: +5%; Min Oper Temp: -55DEGC; Min TC: -200PPM; Min Tol: -5%; Mounting Type: SMD; NOTE Status: PREFERRED; Old Footprint: RESC1005X40N,0402; PCB Package: 0402; Packing Size: 10000; Packing Type: TAPE_&_REEL; Part Number: 01-01244; Part Type: RESISTOR\0402; Resistor Type: THICK FILM; Revision: R001; RoHS Status: ROHS_COMPLIANT; Rtd Power: 0.063W; Rtd Voltage: 50V; WEIGHT: 0.00065g
R3081 = RESISTOR: RESISTOR, THICK FILM, 3.9k, -1%/+1%, 0.063W, 50V, -55DEGC/+155DEGC, 0402, SMD; ALT_SYMBOLS: RESC1005X40L,RESC1005X40M; AutoDoc File: http://notefied-dynamic-precision.com/DB/Apps/Desktop/Item/Object.aspx?id=76730; Budget Currency: USD; Budget Price: 0.00244; Datasheet URL 1: N/A; Datasheet URL 2: N/A; Definied Quality: INDUSTRIAL; Esd Level: N/A; FPLIST: RESC1005X40N,RESC1005X40L,RESC1005X40M; Last Time Buy: N/A; Lead Time: N/A; LifeCycle Status: ACTIVE; MPN: RESISTOR_0402_3.9k_+/-1%_50V_0.063W_M_+/-100PPM; MPN Status: ACTIVE; MSL: N/A; MTBF: N/A; MTBF Standard: N/A; Manufacturer: MANUFACTURER SELECTION; Max Oper Temp: +155DEGC; Max TC: +100PPM/DEGC; Max Tol: +1%; Min Oper Temp: -55DEGC; Min TC: -100PPM/DEGC; Min Tol: -1%; Mounting Type: SMD; NOTE Status: PREFERRED; Old Footprint: RESC1005X40N; PCB Package: 0402; Packing Size: 10000; Packing Type: TAPE_&_REEL; Part Number: 01-12675; Part Type: RESISTOR\0402\PRECISION; Resistor Type: THICK FILM; Revision: R000; RoHS Status: ROHS_COMPLIANT; Rtd Power: 0.063W; Rtd Voltage: 50V; WEIGHT: N/A
SC1 = SHIELD_COVER_BMIS-201: MECHANICAL, FRAME, SMD; AutoDoc File: http://notefied-dynamic-precision.com/DB/Apps/Desktop/Item/Object.aspx?id=92612; Datasheet URL 1: http://lairdtech.thomasnet.com/printbrowser?&plpver=10&prodid=3001092&itemid=2129&assetid=5583&qlty=75&size=100&mode=30; Datasheet URL 2: http://lairdtech.thomasnet.com/printitem/board-level-shielding/standard-surface-mount-shields-two-piece/bmis-201?&plpver=10&assetid=&origin=&by=&filter=; FPLIST: MECH_BMIS201F,; MPN Status: ACTIVE; Manufacturer: LAIRD; Max Oper Temp: N/A; Min Oper Temp: N/A; NOTE Status: PREFERRED; Packing Size: 1000; Packing Type: TAPE_&_REEL; Part Number: 13-00503; Part Type: MECHANIC\SHIELD; Revision: R001; RoHS Status: ROHS_COMPLIANT; WEIGHT: 0.3g
SC2 = SHIELD_COVER_BMIS-201-C: MECHANICAL, COVER, NOT APPLY; AutoDoc File: http://notefied-dynamic-precision.com/DB/Apps/Desktop/Item/Object.aspx?id=92611; Datasheet URL 1: http://lairdtech.thomasnet.com/printbrowser?&plpver=10&prodid=3001092&itemid=2129&assetid=5583&qlty=75&size=100&mode=30; Datasheet URL 2: http://lairdtech.thomasnet.com/printitem/board-level-shielding/standard-surface-mount-shields-two-piece/bmis-201?&plpver=10&assetid=&origin=&by=&filter=; FPLIST: MECH_BMIS201C,; MPN Status: ACTIVE; Manufacturer: LAIRD; Max Oper Temp: N/A; Min Oper Temp: N/A; Mounting Type: NOT APPLY; NOTE Status: PREFERRED; Packing Size: 1000; Packing Type: TAPE_&_REEL; Part Number: 13-00502; Part Type: MECHANIC\SHIELD; Revision: R001; RoHS Status: ROHS_COMPLIANT; WEIGHT: 0.3g
U1 = IC_RF_CC2538SF53_QFN56_V1_0: IC, ANALOG, POWER SYSTEM-ON-CHIP FOR 2.4GHz IEEE 802.15.4 ZigBee, 2V TO 3.6V, -40DEGC/+125 DEGC, VQFN56, SMD; ALT_SYMBOLS: QFNFC50P800X800X100-57AL,QFNFC50P800X800X100-57AM; AutoDoc File: http://notefied-dynamic-precision.com/DB/Apps/Desktop/Item/Object.aspx?id=92716; Budget Currency: USD; Budget Price: 4.68; Datasheet URL 2: http://www.ti.com/lit/ds/symlink/cc2538.pdf; FPLIST: QFNFC50P800X800X100-57AN,QFNFC50P800X800X100-57AL,QFNFC50P800X800X100-57AM; MPN Status: ACTIVE; MSL: 3; MTBF: 3.97*10^8; Manufacturer: TEXAS INSTRUMENTS; Max Oper Temp: +125DEGC; Min Oper Temp: -40DEGC; Mounting Type: SMD; NOTE Status: PREFERRED; PCB Package: VQFN56; Packing Size: 250; Packing Type: TAPE_&_REEL; Part Number: 18-29079; Part Type: IC\ANALOG\RF\TRANSCEIVER\ZIG-BEE; Revision: R001; RoHS Status: ROHS_COMPLIANT; Rtd Voltage: 2V TO 3.6V; WEIGHT: 0.1976g
U2 = IC_PM_TLV700233_SOT23-5: IC, ANALOG, LOW-DROPOUT REGLATOR, VIN:2V TO 5.5V, VOUT:3.3V, SOT23-5, SMD; ALT_SYMBOLS: SOT95P280X145-5L,SOT95P280X145-5M; AutoDoc File: http://notefied-dynamic-precision.com/DB/Apps/Desktop/Item/Object.aspx?id=88801; Budget Currency: USD; Budget Price: 0.14; Datasheet URL 2: http://www.ti.com/lit/ds/symlink/tlv70233.pdf; FPLIST: SOT95P280X145-5N,SOT95P280X145-5L,SOT95P280X145-5M; MPN: TLV70233DBVR; MPN Status: ACTIVE; MSL: 1; MTBF: 4.07* 10^9; Manufacturer: TEXAS INSTRUMENTS; Max Oper Temp: +125DEGC; Min Oper Temp: -40DEGC; Mounting Type: SMD; NOTE Status: PREFERRED; PCB Package: SOT23-5; Packing Size: 3000; Packing Type: TAPE_&_REEL; Part Number: 18-28503; Part Type: IC\ANALOG\PM\REGULATOR; Revision: R001; RoHS Status: ROHS_COMPLIANT; Rtd Current: 0.3A; Rtd Power: 0.5W; Rtd Voltage: 3.3V; WEIGHT: 0.018g
U3 = IC_RF_CC2592_QFN16_2: IC, ANALOG, 2.4GHz RF FRONT END, 2V TO 3.7V, QFN16, SMD; ALT_SYMBOLS: QFNFC65P400X400X100-17AL,QFNFC65P400X400X100-17AM; AutoDoc File: http://notefied-dynamic-precision.com/DB/Apps/Desktop/Item/Object.aspx?id=89421; Frequency: 2.4GHz; MPN Status: PRELIMINARY; Manufacturer: TEXAS INSTRUMENTS; Max Oper Temp: +125DEGC; Min Oper Temp: -40DEGC; Mounting Type: SMD; NOTE Status: PREFERRED; PCB Package: QFN16; Part Number: 18-28661; Part Type: IC\ANALOG\RF\MODULATOR; Revision: R001; RoHS Status: ROHS_COMPLIANT; Rtd Voltage: 2V TO 3.7V
X1 = XTAL_4: CRYSTAL, OSCILATOR, 32MHz, 10pF, -10PPM/+10PPM, -40DEGC/+85DEGC, SMD; Alt IPC Footprints: XTAL_FA128L,XTAL_FA128M; AutoDoc File: https://notefied-dynamic-precision.com/NotefiedWebServices/AutoDocs.aspx?itemid=85460; Capacitance: 10pF; Datasheet URL 1: http://www.epsontoyocom.co.jp/english/product/Crystal/set02/fa128/index.html; Datasheet URL 2: http://ndap3-net.ebz.epson.co.jp/w/www/PDFS/epdoc_qd.nsf/85a4e2c523a1f89349257068002f9e30/255cb2884010a1f9492571f0004c7d72/$FILE/FA-128_E107.pdf; MPN: FA-128 32MHz 10pF 10PPM; MPN Status: ACTIVE; Manufacturer: Epson Toyocom; Max Oper Temp: +85DEGC; Max Tol: +10PPM; Min Oper Temp: -40DEGC; Min Tol: -10PPM; Mounting Type: SMD; NOTE Status: PREFERRED; PCB Package: SMD; Part Number: 12-00422; Part Type: CRYSTAL\OSCILLATOR\MEMS; Revision: R001; RoHS Status: ROHS_COMPLIANT
X2 = XTAL: CRYSTAL, OSCILATOR, 32.768kHz, -20PPM/ + 20PPM, -40DEGC/ +85DEGC, 12.5pF, SMD; ALT_SYMBOLS: XTAL_FC12ML,XTAL_FC12MM; AutoDoc File: https://notefied-dynamic-precision.com/NotefiedWebServices/AutoDocs.aspx?itemid=85632; Capacitance: 12.5pF; Datasheet URL 1: http://ndap3-net.ebz.epson.co.jp/w/www/PDFS/epdoc_qd.nsf/2668203aa9368a6349256a9c001d58b3/737394e88f20bfba4925736b002b4c07/$FILE/FC-12M_E108.pdf; Datasheet URL 2: http://ndap3-net.ebz.epson.co.jp/w/www/PDFS/epdoc_qd.nsf/2668203aa9368a6349256a9c001d58b3/737394e88f20bfba4925736b002b4c07/$FILE/FC-12M_E108.pdf; MPN: FC-12M 32.768kHz 20ppm; Manufacturer: Epson Toyocom; Max Oper Temp: +85DEGC; Max Tol: +20PPM; Min Oper Temp: -40DEGC; Min Tol: -20PPM; Mounting Type: SMD; NOTE Status: PREFERRED; Part Number: 12-00430; Part Type: CRYSTAL\OSCILLATOR\MEMS; Revision: R001; RoHS Status: ROHS_COMPLIANT

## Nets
DVDD_USB: C41.1 P5.3 U1.4(DVDD_USB) U2.5(OUT)
GND: A1.2(GND) A1.3(GND) C2.2 C3.2 C4.2 C5.2 C21.2 C31.2 C41.2 C101.2 C151.2 C241.2 C281.2 C321.2 C331.2 C341.2 C351.2 C361.2 C391.2 C392.2 C431.2 C441.2 C451.2 C551.2 C561.2 C3101.2 C3103.2 C3105.2 C3106.2 C3107.2 C3108.2 C3109.2 C3131.2 C3132.2 C3133.2 J1.5(GND) J1.6(GND) J1.7(GND) J1.8(GND) J1.9(GND) J1.10(GND) J1.11(GND) J3.2 J3.3 J3.4 J3.5 P1.1 P1.19 P2.2 P2.20 R1.1 R421.1 R3081.1 SC1.1(GND) SC1.2(GND) SC1.3(GND) SC1.4(GND) SC1.5(GND) SC1.6(GND) SC1.7(GND) SC1.8(GND) U1.1(DGND_USB) U1.57(AGND) U2.2(GND) U3.1(GND) U3.4(GND) U3.9(GND) U3.11(GND) U3.12(GND) U3.16(GND) U3.17(EGP/GND) X1.2 X1.4
VDD_CC2538: C2.1 C4.1 C101.1 C151.1 C241.1 C331.1 C361.1 C391.1 C392.1 C431.1 C551.1 FL1.1 U1.10(DVDD) U1.15(DVDD) U1.24(DVDD) U1.33(AVDD) U1.36(AVDD) U1.39(AVDD) U1.40(AVDD) U1.41(AVDD) U1.43(AVDD_GUARD) U1.55(DVDD)
VDD_CC2592: C5.1 C3106.1 C3107.1 C3108.1 C3131.1 C3132.1 C3133.1 FL2.1 L3101.1 U3.13(VDD_LNA) U3.14(VDD_BIAS) U3.15(VDD_PA)
VDD_EB: P2.7 P2.9 P5.2
JTAG_TCK: P2.1 U1.47(JTAG_TCK)
JTAG_TMS: P2.4 U1.46(JTAG_TMS)
nRESET: P2.15 R281.1
PA0: P1.7 U1.16(PA0)
PA1: P1.9 U1.17(PA1)
PA2: P1.16 U1.18(PA2)
PA3: P1.14 U1.19(PA3)
PA4: P1.18 U1.20(PA4)
PA5: P1.20 U1.21(PA5)
PA6: P2.5 U1.22(PA6)
PA7: P2.6 U1.23(PA7)
PB0: P1.3 U1.5(PB0)
PB1: P1.5 U1.54(PB1)
PB2: P1.11 U1.53(PB2)
PB3: P1.13 U1.52(PB3)
PB4: P1.15 U1.51(PB4)
PB5: P1.17 U1.50(PB5)
PB6/JTAG_TDI: P2.17 U1.49(PB6)
PB7/JTAG_TDO: P2.19 U1.48(PB7)
PC0: P2.11 R32.2 U1.14(PC0)
PC1: P2.13 U1.13(PC1)
PC2: R121.1 R3061.1 U1.12(PC2)
PC3: R111.1 R3051.1 U1.11(PC3)
PC4: P1.6 U1.9(PC4)
PC5: P1.8 U1.8(PC5)
PC6: P1.10 U1.7(PC6)
PC7: P1.12 U1.6(PC7)
PD0: P2.12 U1.25(PD0)
PD1: P2.14 U1.26(PD1)
PD2: R271.2 R3071.1 U1.27(PD2)
PD3: P2.18 U1.29(PD3)
PD4: P2.8 U1.30(PD4)
PD5: P2.10 U1.31(PD5)
PD6: P6.1 R442.1
PD7: P6.2 R452.1
USB_N: C21.1 R21.1 U1.3(USB_N)
USB_P: C31.1 R31.1 U1.2(USB_P)
N05346: R421.2 U1.42(R_BIAS)
N19179: J1.3(D+) R31.2 R32.1
N23099: C341.1 U1.34(XOSC32M_Q1) X1.1
N24069: J1.4(ID) R1.2
N28244: J1.2(D-) R21.2
N31525: C351.1 U1.35(XOSC32M_Q2) X1.3
N50825: C3.1 J1.1(VBUS) U2.1(IN) U2.3(EN)
N61958: P2.16 R271.1
N118182: FL1.2 FL2.2 P5.1
N130966: R3081.2 U3.8(BIAS)
N292030: P1.2 R121.2
N292096: P1.4 R111.2
N302598: A1.1(FEED) C3109.1 C3110.2
N313805: L3231.1 U1.37(RF_P) U3.3(RF_P)
N313817: L3231.2 U1.38(RF_N) U3.2(RF_N)
N314459: R3071.2 U3.7(HGM)
N314634: R3061.2 U3.6(LNA_EN)
N315094: R3051.2 U3.5(PA_EN)
N333392: C3101.1 L3101.2 L3102.1 U3.10(ANT)
N333448: C3105.1 C3110.1 C3111.2 L3104.2
N333456: C3103.1 L3102.2 L3104.1
N355972: C3111.1 J3.1
N359155: C441.1 R441.2 X2.1
N359159: C451.1 R451.2 X2.2
N359209: R451.1 R452.2 U1.45(PD7/XOSC32K_Q2)
N359245: R441.1 R442.2 U1.44(PD6/XOSC32K_Q1)
N359999: C281.1 R281.2 U1.28(nRESET)
N362623: C321.1 C561.1 U1.32(DCOUPL2) U1.56(DCOUPL1)

Not connected (* = marked no-connect by the designer): FIDU1 1*; FIDU2 1*; FIDU3 1*; FIDU4 1*; FIDU5 1*; FIDU6 1*; P2 3; P5 4*; U2 4(NC)*

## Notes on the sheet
- USB interface
- External pull-up resistor
  driven by PC0
- Place close
  to pin10
- Place close
  to pin15
- Place close
  to pin24
- Place close
  to pin33
- Place close
  to pin36
- Place close
  to pin 39, 40
  and 41
- Place close
  to pin43
- Place close
  to pin55
- Placeholder for
  a large capacitor
  if needed close to
  power supply
- Mount either
  C3111 or C3110 = 18 pF
  to select SMA or PCB ant.
- Pinrow for GPIOs not available
  from EM connector 1 and 2.
  Not mounted
- EM connector 1
- EM connector 2
